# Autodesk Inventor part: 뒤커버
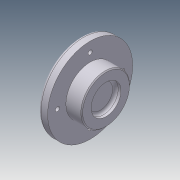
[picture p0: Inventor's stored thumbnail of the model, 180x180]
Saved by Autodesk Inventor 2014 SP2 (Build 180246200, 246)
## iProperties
Company: 한국ATC센터
Created: 2014-11
Part Number: 뒤커버
Document SubType Name: Modeling
Designer: KYOUNG IL JANG
Density: 2.71 g/cm^3
Material: 알루미늄-6061
Mass: 280.898 g
Surface Area: 198.677 cm^2
Volume: 103.653 cm^3
Appearance: 알루미늄 - 평지
Author: KYOUNG IL JANG
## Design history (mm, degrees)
sketch "스케치1"
  geometry: L1 (-13.5, 0)-(13.5, 0); L2 (-13.5, 0)-(-13.5, 45.5); L3 (-13.5, 45.5)-(-3.5, 45.5); L4 (-3.5, 45.5)-(-3.5, 26); L5 (-3.5, 26)-(13.5, 26); L6 (13.5, 26)-(13.5, 0); 2 further points
  constraints: 12 end point, 3 parallel, 2 perpendicular, 1 coincident, 1 horizontal, 1 midpoint
  dimensions: "d0" = 27 distance of L1.start L1.end; "d1" = 91 diameter of L3 L1; "d2" = 52 diameter of L5 L1; "d3" = 10 distance of L2.end L3.end
revolve "회전1" sketch "스케치1" stored, may be unused: angle "d4" = 90 deg
sketch "스케치2"
  geometry: 2 further points
  constraints: 1 vertical alignment
  dimensions: "d14" = 35 distance of point (0, 0) point (0, 35)
hole "구멍2" sketch "스케치2" at (0, 35) diameter "d15" = 4.5; stored, may be unused: countersink angle "d19" = 90 deg, drill point angle "d21" = 118 deg; dims "d16" = 6, "d17" = 8, "d18" = 4.4, "d20" = 8
fillet "모깎기1" dims "d29" = 3
chamfer "모따기2" distance "d30" = 1; stored, may be unused: second distance "d31" = 2, angle "d32" = 30 deg
sketch "스케치3"
  geometry: L1 (-22.444, 6.652)-(-10, 14.967); L2 (-22.444, -6.652)-(-10, -14.967); L3 (10, -14.967)-(22.444, -6.652); L4 (22.444, 6.652)-(10, 14.967); A1 r 18 centre (0, 0) between (-18, 0) and (18, 0); A2 r 8 centre (18, 0) between (22.444, -6.652) and (22.444, 6.652); A3 r 8 centre (-18, 0) between (-22.444, 6.652) and (-22.444, -6.652); 1 further point
  constraints: 10 point on circle, 8 end point, 6 tangent, 3 centre point, 2 horizontal alignment, 2 parallel, 1 coincident, 1 equal radius
  dimensions: "d36" = 36 diameter of A1; "d37" = 16 diameter of A2
extrude "돌출1" join sketch "스케치3" distance "d38" = 7; taper "d39" = 0 deg
hole "구멍3" diameter "d43" = 32; stored, may be unused: countersink angle "d47" = 90 deg, drill point angle "d49" = 0 deg; dims "d41" = 10, "d42" = 10, "d44" = 6, "d45" = 4, "d46" = 2, "d48" = 6
fillet "모깎기2" dims "d40" = 3
node "솔리드1"
pattern_circular "원형 패턴2" dims angle "d34" = 360 deg
